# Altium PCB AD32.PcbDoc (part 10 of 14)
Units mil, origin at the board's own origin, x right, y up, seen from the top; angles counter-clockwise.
Board outline 7007.87 x 4368.85 mil, 12 copper layers (Top Layer, Int1 (GND), Int2 (AVDD), Int3 (DVDD), Int4 (GND), Int5 (ST), Int6 (SB), Int8 (AGND), Int7 (AVCC), Int9 (VCCA), Int10 (GND), Bottom Layer), stack 60.136 mil thick; 1350 components, 880 nets, 4712 pads, 2835 vias.
Unrouted connection lines stored in the file: 19.
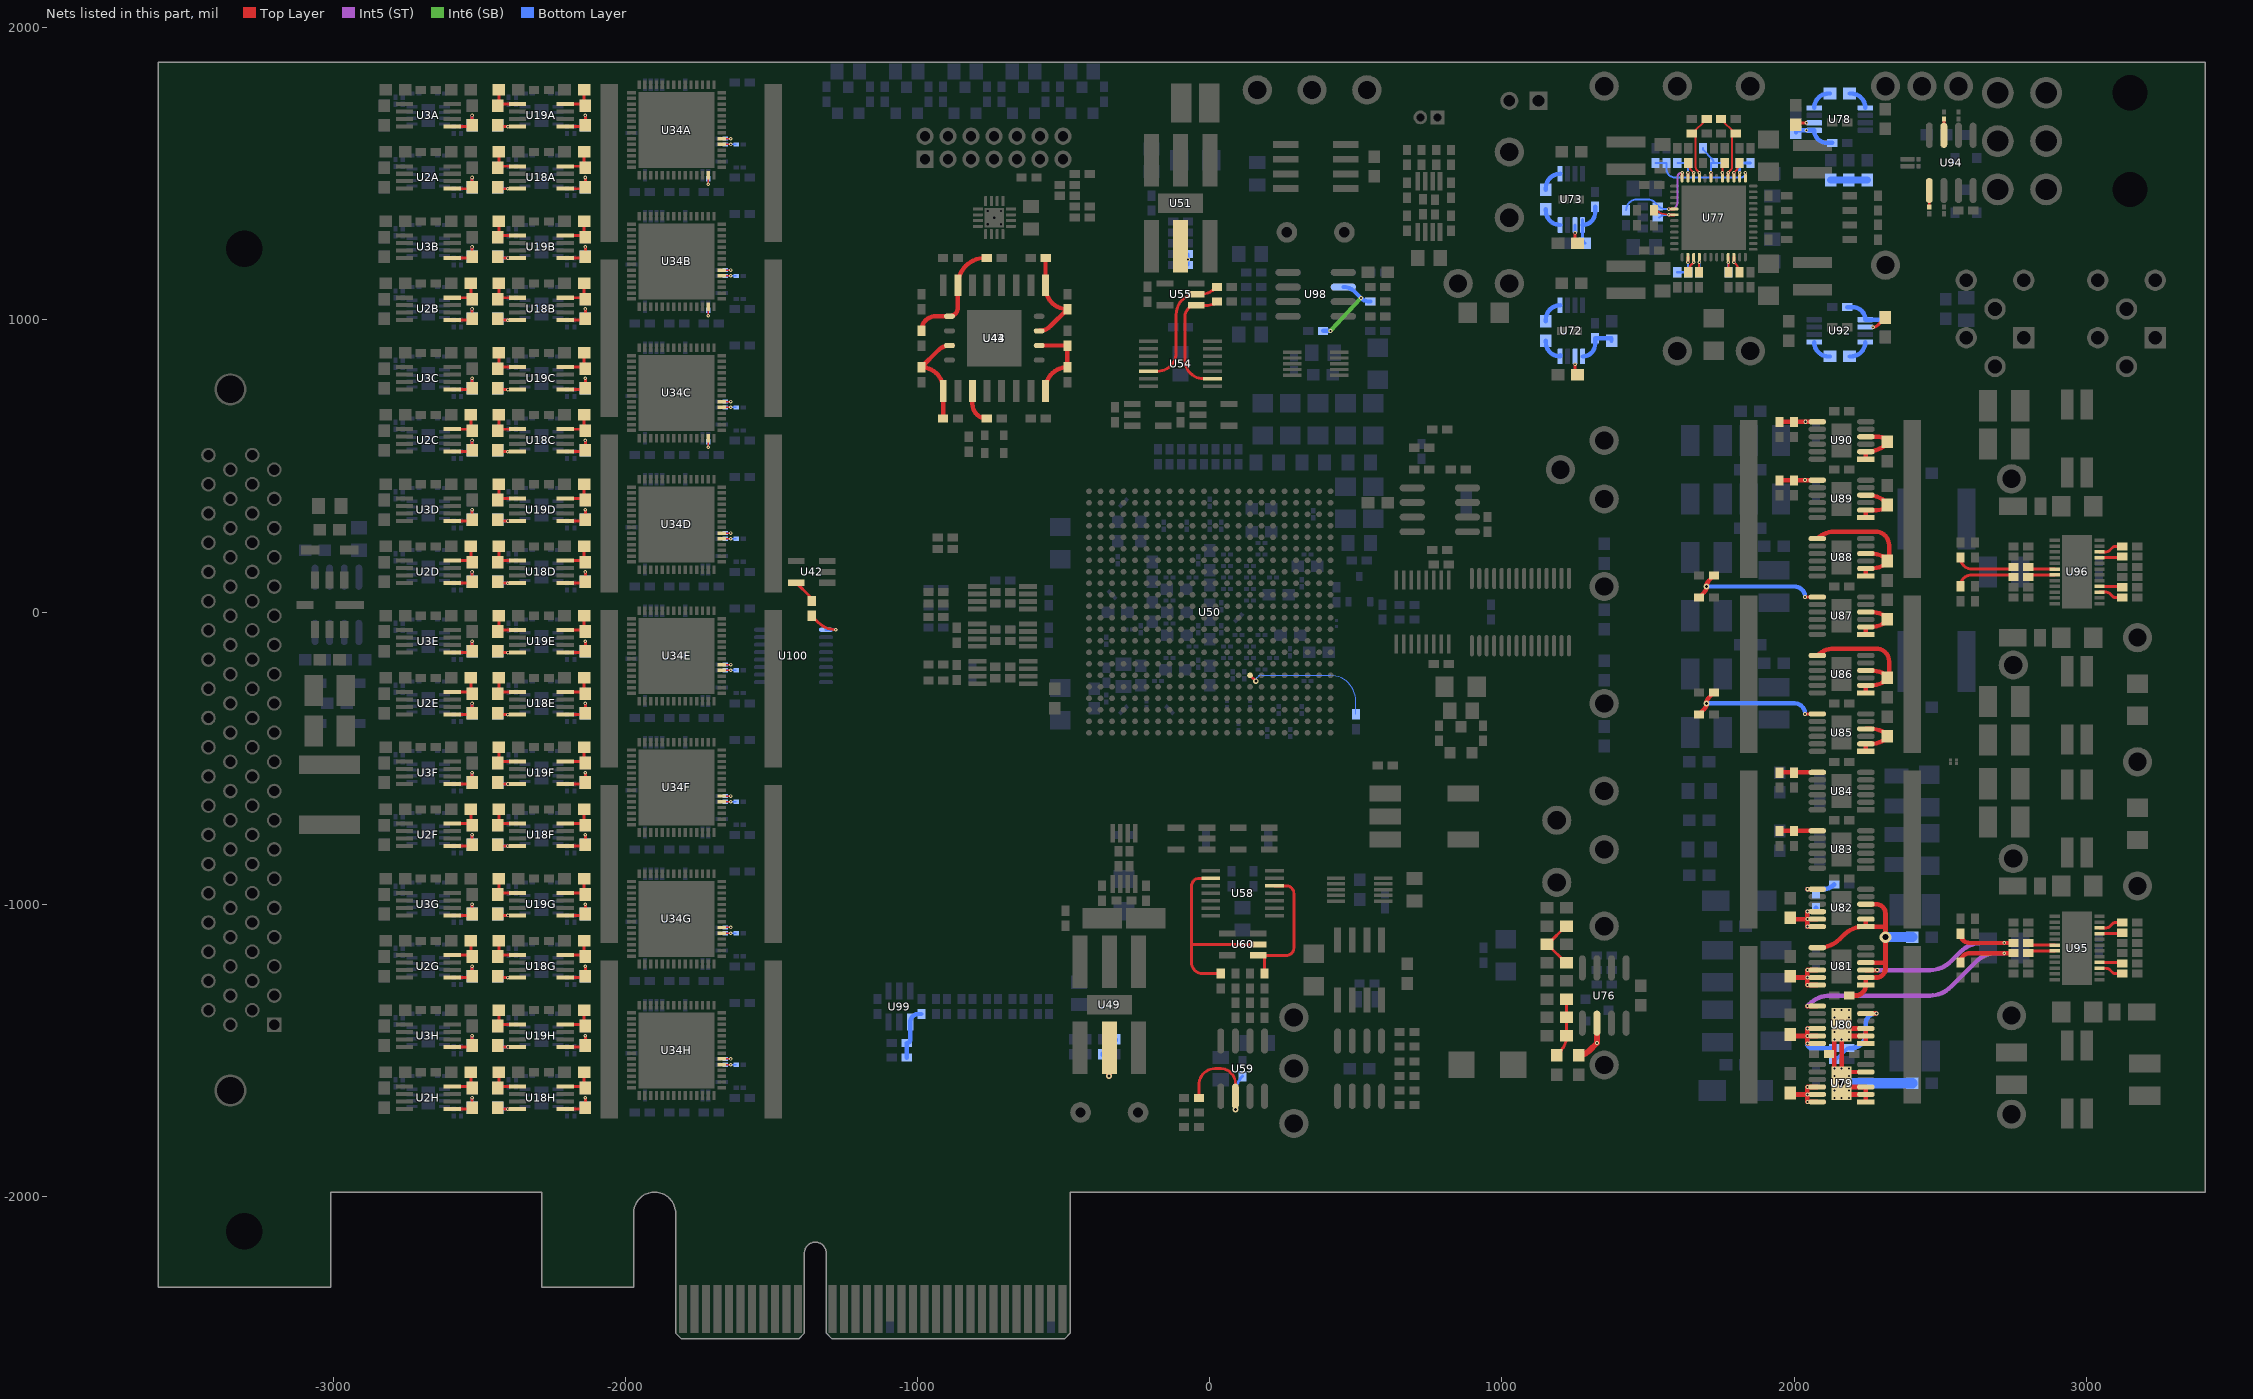
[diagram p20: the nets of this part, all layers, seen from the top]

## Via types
v1: diameter 12, hole 6, Top Layer to Bottom Layer, tented both sides, 1497 vias
v2: diameter 20, hole 10, Top Layer to Bottom Layer, tented both sides, 364 vias
v3: diameter 19, hole 10, Top Layer to Bottom Layer, tented both sides, 347 vias
v4: diameter 14, hole 7, Top Layer to Bottom Layer, tented both sides, 228 vias
v5: diameter 19.68, hole 7.87, Top Layer to Bottom Layer, 225 vias
v6: diameter 19.02, hole 10, Top Layer to Bottom Layer, tented both sides, 85 vias
v7: diameter 20, hole 10, Top Layer to Bottom Layer, 32 vias
v8: diameter 40, hole 20, Top Layer to Bottom Layer, tented both sides, 14 vias
v9: diameter 30, hole 15, Top Layer to Bottom Layer, tented both sides, 12 vias
v10: diameter 25, hole 13, Top Layer to Bottom Layer, 8 vias
v11: diameter 40, hole 20, Top Layer to Bottom Layer, 6 vias
v12: diameter 50, hole 20, Top Layer to Bottom Layer, 6 vias
v13: diameter 66, hole 47, Top Layer to Bottom Layer, tented both sides, 3 vias
v14: diameter 63, hole 45, Top Layer to Bottom Layer, 2 vias
v15: diameter 50, hole 25, Top Layer to Bottom Layer, 2 vias
v16: diameter 12, hole 6, Top Layer to Bottom Layer, 2 vias
v17: diameter 60, hole 40, Top Layer to Bottom Layer, tented both sides, 1 vias
v18: diameter 60, hole 40, Top Layer to Bottom Layer, 1 vias

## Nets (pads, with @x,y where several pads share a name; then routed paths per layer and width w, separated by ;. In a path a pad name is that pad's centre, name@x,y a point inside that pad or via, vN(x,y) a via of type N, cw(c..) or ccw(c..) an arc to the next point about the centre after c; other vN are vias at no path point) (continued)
NetR44B_1: R44B.1 R60B.2 U2B.4 | length 118.6
  Top Layer w10: U2B.4@-2593.31,1075.89 -2530.92,1075.89 R60B.2@-2529.92,1076.89 ; R60B.2@-2529.04,1076 -2525,1071.97 R60B.2@-2525,1070.96 ; R60B.2@-2529.04,1076.89 R44B.1@-2529.04,1125
NetR44C_1: R44C.1 R60C.2 U2C.4 | length 118.6
  Top Layer w10: U2C.4@-2593.31,625.89 -2530.92,625.89 R60C.2@-2529.92,626.89 ; R60C.2@-2529.04,626 -2525,621.97 R60C.2@-2525,620.96 ; R60C.2@-2529.04,626.89 R44C.1@-2529.04,675
NetR44D_1: R44D.1 R60D.2 U2D.4 | length 118.6
  Top Layer w10: U2D.4@-2593.31,175.89 -2530.92,175.89 R60D.2@-2529.92,176.89 ; R60D.2@-2529.04,176 -2525,171.97 R60D.2@-2525,170.96 ; R60D.2@-2529.04,176.89 R44D.1@-2529.04,225
NetR44E_1: R44E.1 R60E.2 U2E.4 | length 118.6
  Top Layer w10: U2E.4@-2593.31,-274.11 -2530.92,-274.11 R60E.2@-2529.92,-273.11 ; R60E.2@-2529.04,-274 -2525,-278.03 R60E.2@-2525,-279.04 ; R60E.2@-2529.04,-273.11 R44E.1@-2529.04,-225
NetR44F_1: R44F.1 R60F.2 U2F.4 | length 118.6
  Top Layer w10: U2F.4@-2593.31,-724.11 -2530.92,-724.11 R60F.2@-2529.92,-723.11 ; R60F.2@-2529.04,-724 -2525,-728.03 R60F.2@-2525,-729.04 ; R60F.2@-2529.04,-723.11 R44F.1@-2529.04,-675
NetR44G_1: R44G.1 R60G.2 U2G.4 | length 118.6
  Top Layer w10: U2G.4@-2593.31,-1174.11 -2530.92,-1174.11 R60G.2@-2529.92,-1173.11 ; R60G.2@-2529.04,-1174 -2525,-1178.03 R60G.2@-2525,-1179.04 ; R60G.2@-2529.04,-1173.11 R44G.1@-2529.04,-1125
NetR44H_1: R44H.1 R60H.2 U2H.4 | length 118.6
  Top Layer w10: U2H.4@-2593.31,-1624.11 -2530.92,-1624.11 R60H.2@-2529.92,-1623.11 ; R60H.2@-2529.04,-1624 -2525,-1628.03 R60H.2@-2525,-1629.04 ; R60H.2@-2529.04,-1623.11 R44H.1@-2529.04,-1575
NetR52A_1: R52A.1 R609A.2 U3A.1 | length 136.6
  Top Layer w10: U3A.1@-2593.31,1661.49 -2537.18,1661.49 ccw(c-2537.18,1678.72) R52A.1@-2525,1666.54 v1(-2525,1700)
  Bottom Layer w10: R609A.2@-2525,1666.54 v1(-2525,1700)
NetR52B_1: R52B.1 R609B.2 U3B.1 | length 136.6
  Top Layer w10: U3B.1@-2593.31,1211.49 -2537.18,1211.49 ccw(c-2537.18,1228.72) R52B.1@-2525,1216.54 v1(-2525,1250)
  Bottom Layer w10: R609B.2@-2525,1216.54 v1(-2525,1250)
NetR52C_1: R52C.1 R609C.2 U3C.1 | length 136.6
  Top Layer w10: U3C.1@-2593.31,761.49 -2537.18,761.49 ccw(c-2537.18,778.72) R52C.1@-2525,766.54 v1(-2525,800)
  Bottom Layer w10: R609C.2@-2525,766.54 v1(-2525,800)
NetR52D_1: R52D.1 R609D.2 U3D.1 | length 136.6
  Top Layer w10: U3D.1@-2593.31,311.49 -2537.18,311.49 ccw(c-2537.18,328.72) R52D.1@-2525,316.54 v1(-2525,350)
  Bottom Layer w10: R609D.2@-2525,316.54 v1(-2525,350)
NetR52E_1: R52E.1 R609E.2 U3E.1 | length 136.6
  Top Layer w10: U3E.1@-2593.31,-138.51 -2537.18,-138.51 ccw(c-2537.18,-121.28) R52E.1@-2525,-133.46 v1(-2525,-100)
  Bottom Layer w10: R609E.2@-2525,-133.46 v1(-2525,-100)
NetR52F_1: R52F.1 R609F.2 U3F.1 | length 136.6
  Top Layer w10: U3F.1@-2593.31,-588.51 -2537.18,-588.51 ccw(c-2537.18,-571.28) R52F.1@-2525,-583.46 v1(-2525,-550)
  Bottom Layer w10: R609F.2@-2525,-583.46 v1(-2525,-550)
NetR52G_1: R52G.1 R609G.2 U3G.1 | length 136.6
  Top Layer w10: U3G.1@-2593.31,-1038.51 -2537.18,-1038.51 ccw(c-2537.18,-1021.28) R52G.1@-2525,-1033.46 v1(-2525,-1000)
  Bottom Layer w10: R609G.2@-2525,-1033.46 v1(-2525,-1000)
NetR52H_1: R52H.1 R609H.2 U3H.1 | length 136.6
  Top Layer w10: U3H.1@-2593.31,-1488.51 -2537.18,-1488.51 ccw(c-2537.18,-1471.28) R52H.1@-2525,-1483.46 v1(-2525,-1450)
  Bottom Layer w10: R609H.2@-2525,-1483.46 v1(-2525,-1450)
NetR60A_1: R60A.1 R601A.2 U2A.1 | length 136.6
  Top Layer w10: U2A.1@-2593.31,1449.11 -2536.88,1449.11 ccw(c-2536.88,1465.92) R60A.1@-2525,1454.04 v1(-2525,1487.5)
  Bottom Layer w10: R601A.2@-2525,1454.04 v1(-2525,1487.5)
NetR60B_1: R60B.1 R601B.2 U2B.1 | length 136.6
  Top Layer w10: U2B.1@-2593.31,999.11 -2536.88,999.11 ccw(c-2536.88,1015.92) R60B.1@-2525,1004.04 v1(-2525,1037.5)
  Bottom Layer w10: R601B.2@-2525,1004.04 v1(-2525,1037.5)
NetR60C_1: R60C.1 R601C.2 U2C.1 | length 136.6
  Top Layer w10: U2C.1@-2593.31,549.11 -2536.88,549.11 ccw(c-2536.88,565.92) R60C.1@-2525,554.04 v1(-2525,587.5)
  Bottom Layer w10: R601C.2@-2525,554.04 v1(-2525,587.5)
NetR60D_1: R60D.1 R601D.2 U2D.1 | length 136.6
  Top Layer w10: U2D.1@-2593.31,99.11 -2536.88,99.11 ccw(c-2536.88,115.92) R60D.1@-2525,104.04 v1(-2525,137.5)
  Bottom Layer w10: R601D.2@-2525,104.04 v1(-2525,137.5)
NetR60E_1: R60E.1 R601E.2 U2E.1 | length 136.6
  Top Layer w10: U2E.1@-2593.31,-350.89 -2536.88,-350.89 ccw(c-2536.88,-334.08) R60E.1@-2525,-345.96 v1(-2525,-312.5)
  Bottom Layer w10: R601E.2@-2525,-345.96 v1(-2525,-312.5)
NetR60F_1: R60F.1 R601F.2 U2F.1 | length 136.6
  Top Layer w10: U2F.1@-2593.31,-800.89 -2536.88,-800.89 ccw(c-2536.88,-784.08) R60F.1@-2525,-795.96 v1(-2525,-762.5)
  Bottom Layer w10: R601F.2@-2525,-795.96 v1(-2525,-762.5)
NetR60G_1: R60G.1 R601G.2 U2G.1 | length 136.6
  Top Layer w10: U2G.1@-2593.31,-1250.89 -2536.88,-1250.89 ccw(c-2536.88,-1234.08) R60G.1@-2525,-1245.96 v1(-2525,-1212.5)
  Bottom Layer w10: R601G.2@-2525,-1245.96 v1(-2525,-1212.5)
NetR60H_1: R60H.1 R601H.2 U2H.1 | length 136.6
  Top Layer w10: U2H.1@-2593.31,-1700.89 -2536.88,-1700.89 ccw(c-2536.88,-1684.08) R60H.1@-2525,-1695.96 v1(-2525,-1662.5)
  Bottom Layer w10: R601H.2@-2525,-1695.96 v1(-2525,-1662.5)
NetR68A_1: R68A.1 R593A.2 U19A.8 | length 107.4
  Top Layer w10: R68A.1@-2437.5,1667.04 ccw(c-2432.58,1667.04) -2432.58,1662.11 -2402.5,1662.11 U19A.8@-2369.19,1662.11
  Bottom Layer w10: R593A.2@-2437.5,1666.54 ccw(c-2425.62,1678.42) -2425.62,1661.61 v1(-2402.5,1661.61)
NetR68A_2: R68A.2 R84A.1 U19A.5 | length 127.5
  Top Layer w10: R68A.2@-2433.46,1738.39 R68A.2@-2433.46,1738.31 ; R68A.2@-2433.46,1738.81 cw(c-2432.58,1733.96) -2432.58,1738.89 U19A.5@-2369.19,1738.89 ; R68A.2@-2433.46,1738.89 R84A.1@-2433.46,1788 ; R68A.2@-2433.46,1738.31 ccw(c-2432.58,1733.46) R68A.2@-2437.5,1733.46 ccw(c-2437.5,1737.5) -2433.46,1737.5 R68A.2@-2433.46,1738.31
NetR68B_1: R68B.1 R593B.2 U19B.8 | length 107.4
  Top Layer w10: R68B.1@-2437.5,1217.04 ccw(c-2432.58,1217.04) -2432.58,1212.11 -2402.5,1212.11 U19B.8@-2369.19,1212.11
  Bottom Layer w10: R593B.2@-2437.5,1216.54 ccw(c-2425.62,1228.42) -2425.62,1211.61 v1(-2402.5,1211.61)
NetR68B_2: R68B.2 R84B.1 U19B.5 | length 127.5
  Top Layer w10: R68B.2@-2433.46,1288.39 R68B.2@-2433.46,1288.31 ; R68B.2@-2433.46,1288.81 cw(c-2432.58,1283.96) -2432.58,1288.89 U19B.5@-2369.19,1288.89 ; R68B.2@-2433.46,1288.89 R84B.1@-2433.46,1338 ; R68B.2@-2433.46,1288.31 ccw(c-2432.58,1283.46) R68B.2@-2437.5,1283.46 ccw(c-2437.5,1287.5) -2433.46,1287.5 R68B.2@-2433.46,1288.31
NetR68C_1: R68C.1 R593C.2 U19C.8 | length 107.4
  Top Layer w10: R68C.1@-2437.5,767.04 ccw(c-2432.58,767.04) -2432.58,762.11 -2402.5,762.11 U19C.8@-2369.19,762.11
  Bottom Layer w10: R593C.2@-2437.5,766.54 ccw(c-2425.62,778.42) -2425.62,761.61 v1(-2402.5,761.61)
NetR68C_2: R68C.2 R84C.1 U19C.5 | length 127.5
  Top Layer w10: R68C.2@-2433.46,838.39 R68C.2@-2433.46,838.31 ; R68C.2@-2433.46,838.81 cw(c-2432.58,833.96) -2432.58,838.89 U19C.5@-2369.19,838.89 ; R68C.2@-2433.46,838.89 R84C.1@-2433.46,888 ; R68C.2@-2433.46,838.31 ccw(c-2432.58,833.46) R68C.2@-2437.5,833.46 ccw(c-2437.5,837.5) -2433.46,837.5 R68C.2@-2433.46,838.31
NetR68D_1: R68D.1 R593D.2 U19D.8 | length 107.4
  Top Layer w10: R68D.1@-2437.5,317.04 ccw(c-2432.58,317.04) -2432.58,312.11 -2402.5,312.11 U19D.8@-2369.19,312.11
  Bottom Layer w10: R593D.2@-2437.5,316.54 ccw(c-2425.62,328.42) -2425.62,311.61 v1(-2402.5,311.61)
NetR68D_2: R68D.2 R84D.1 U19D.5 | length 127.5
  Top Layer w10: R68D.2@-2433.46,388.39 R68D.2@-2433.46,388.31 ; R68D.2@-2433.46,388.81 cw(c-2432.58,383.96) -2432.58,388.89 U19D.5@-2369.19,388.89 ; R68D.2@-2433.46,388.89 R84D.1@-2433.46,438 ; R68D.2@-2433.46,388.31 ccw(c-2432.58,383.46) R68D.2@-2437.5,383.46 ccw(c-2437.5,387.5) -2433.46,387.5 R68D.2@-2433.46,388.31
NetR68E_1: R68E.1 R593E.2 U19E.8 | length 107.4
  Top Layer w10: R68E.1@-2437.5,-132.96 ccw(c-2432.58,-132.96) -2432.58,-137.89 -2402.5,-137.89 U19E.8@-2369.19,-137.89
  Bottom Layer w10: R593E.2@-2437.5,-133.46 ccw(c-2425.62,-121.58) -2425.62,-138.39 v1(-2402.5,-138.39)
NetR68E_2: R68E.2 R84E.1 U19E.5 | length 127.5
  Top Layer w10: R68E.2@-2433.46,-61.61 R68E.2@-2433.46,-61.69 ; R68E.2@-2433.46,-61.19 cw(c-2432.58,-66.04) -2432.58,-61.11 U19E.5@-2369.19,-61.11 ; R68E.2@-2433.46,-61.11 R84E.1@-2433.46,-12 ; R68E.2@-2433.46,-61.69 ccw(c-2432.58,-66.54) R68E.2@-2437.5,-66.54 ccw(c-2437.5,-62.5) -2433.46,-62.5 R68E.2@-2433.46,-61.69
NetR68F_1: R68F.1 R593F.2 U19F.8 | length 107.4
  Top Layer w10: R68F.1@-2437.5,-582.96 ccw(c-2432.58,-582.96) -2432.58,-587.89 -2402.5,-587.89 U19F.8@-2369.19,-587.89
  Bottom Layer w10: R593F.2@-2437.5,-583.46 ccw(c-2425.62,-571.58) -2425.62,-588.39 v1(-2402.5,-588.39)
NetR68F_2: R68F.2 R84F.1 U19F.5 | length 127.5
  Top Layer w10: R68F.2@-2433.46,-511.61 R68F.2@-2433.46,-511.69 ; R68F.2@-2433.46,-511.19 cw(c-2432.58,-516.04) -2432.58,-511.11 U19F.5@-2369.19,-511.11 ; R68F.2@-2433.46,-511.11 R84F.1@-2433.46,-462 ; R68F.2@-2433.46,-511.69 ccw(c-2432.58,-516.54) R68F.2@-2437.5,-516.54 ccw(c-2437.5,-512.5) -2433.46,-512.5 R68F.2@-2433.46,-511.69
NetR68G_1: R68G.1 R593G.2 U19G.8 | length 107.4
  Top Layer w10: R68G.1@-2437.5,-1032.96 ccw(c-2432.58,-1032.96) -2432.58,-1037.89 -2402.5,-1037.89 U19G.8@-2369.19,-1037.89
  Bottom Layer w10: R593G.2@-2437.5,-1033.46 ccw(c-2425.62,-1021.58) -2425.62,-1038.39 v1(-2402.5,-1038.39)
NetR68G_2: R68G.2 R84G.1 U19G.5 | length 127.5
  Top Layer w10: R68G.2@-2433.46,-961.61 R68G.2@-2433.46,-961.69 ; R68G.2@-2433.46,-961.19 cw(c-2432.58,-966.04) -2432.58,-961.11 U19G.5@-2369.19,-961.11 ; R68G.2@-2433.46,-961.11 R84G.1@-2433.46,-912 ; R68G.2@-2433.46,-961.69 ccw(c-2432.58,-966.54) R68G.2@-2437.5,-966.54 ccw(c-2437.5,-962.5) -2433.46,-962.5 R68G.2@-2433.46,-961.69
NetR68H_1: R68H.1 R593H.2 U19H.8 | length 107.4
  Top Layer w10: R68H.1@-2437.5,-1482.96 ccw(c-2432.58,-1482.96) -2432.58,-1487.89 -2402.5,-1487.89 U19H.8@-2369.19,-1487.89
  Bottom Layer w10: R593H.2@-2437.5,-1483.46 ccw(c-2425.62,-1471.58) -2425.62,-1488.39 v1(-2402.5,-1488.39)
NetR68H_2: R68H.2 R84H.1 U19H.5 | length 127.5
  Top Layer w10: R68H.2@-2433.46,-1411.61 R68H.2@-2433.46,-1411.69 ; R68H.2@-2433.46,-1411.19 cw(c-2432.58,-1416.04) -2432.58,-1411.11 U19H.5@-2369.19,-1411.11 ; R68H.2@-2433.46,-1411.11 R84H.1@-2433.46,-1362 ; R68H.2@-2433.46,-1411.69 ccw(c-2432.58,-1416.54) R68H.2@-2437.5,-1416.54 ccw(c-2437.5,-1412.5) -2433.46,-1412.5 R68H.2@-2433.46,-1411.69
NetR76A_1: R76A.1 R585A.2 U18A.8 | length 108.5
  Top Layer w10: R76A.1@-2437.5,1454.04 ccw(c-2432.58,1454.04) -2432.58,1449.11 v1(-2402.89,1449.11) U18A.8@-2369.19,1449.11
  Bottom Layer w10: R585A.2@-2437.5,1454.04 ccw(c-2432.58,1454.04) -2432.58,1449.11 v1(-2402.89,1449.11)
NetR76A_2: R76A.2 R92A.1 U18A.5 | length 124.7
  Top Layer w10: R92A.1@-2433.46,1575 -2433.46,1530.71 cw(c-2447.24,1530.71) R76A.2@-2437.5,1520.96 cw(c-2425.62,1509.08) -2425.62,1525.89 U18A.5@-2369.19,1525.89
NetR76B_1: R76B.1 R585B.2 U18B.8 | length 108.5
  Top Layer w10: R76B.1@-2437.5,1004.04 ccw(c-2432.58,1004.04) -2432.58,999.11 v1(-2402.89,999.11) U18B.8@-2369.19,999.11
  Bottom Layer w10: R585B.2@-2437.5,1004.04 ccw(c-2432.58,1004.04) -2432.58,999.11 v1(-2402.89,999.11)
NetR76B_2: R76B.2 R92B.1 U18B.5 | length 124.7
  Top Layer w10: R92B.1@-2433.46,1125 -2433.46,1080.71 cw(c-2447.24,1080.71) R76B.2@-2437.5,1070.96 cw(c-2425.62,1059.08) -2425.62,1075.89 U18B.5@-2369.19,1075.89
NetR76C_1: R76C.1 R585C.2 U18C.8 | length 108.5
  Top Layer w10: R76C.1@-2437.5,554.04 ccw(c-2432.58,554.04) -2432.58,549.11 v1(-2402.89,549.11) U18C.8@-2369.19,549.11
  Bottom Layer w10: R585C.2@-2437.5,554.04 ccw(c-2432.58,554.04) -2432.58,549.11 v1(-2402.89,549.11)
NetR76C_2: R76C.2 R92C.1 U18C.5 | length 124.7
  Top Layer w10: R92C.1@-2433.46,675 -2433.46,630.71 cw(c-2447.24,630.71) R76C.2@-2437.5,620.96 cw(c-2425.62,609.08) -2425.62,625.89 U18C.5@-2369.19,625.89
NetR76D_1: R76D.1 R585D.2 U18D.8 | length 108.5
  Top Layer w10: R76D.1@-2437.5,104.04 ccw(c-2432.58,104.04) -2432.58,99.11 v1(-2402.89,99.11) U18D.8@-2369.19,99.11
  Bottom Layer w10: R585D.2@-2437.5,104.04 ccw(c-2432.58,104.04) -2432.58,99.11 v1(-2402.89,99.11)
NetR76D_2: R76D.2 R92D.1 U18D.5 | length 124.7
  Top Layer w10: R92D.1@-2433.46,225 -2433.46,180.71 cw(c-2447.24,180.71) R76D.2@-2437.5,170.96 cw(c-2425.62,159.08) -2425.62,175.89 U18D.5@-2369.19,175.89
NetR76E_1: R76E.1 R585E.2 U18E.8 | length 108.5
  Top Layer w10: R76E.1@-2437.5,-345.96 ccw(c-2432.58,-345.96) -2432.58,-350.89 v1(-2402.89,-350.89) U18E.8@-2369.19,-350.89
  Bottom Layer w10: R585E.2@-2437.5,-345.96 ccw(c-2432.58,-345.96) -2432.58,-350.89 v1(-2402.89,-350.89)
NetR76E_2: R76E.2 R92E.1 U18E.5 | length 124.7
  Top Layer w10: R92E.1@-2433.46,-225 -2433.46,-269.29 cw(c-2447.24,-269.29) R76E.2@-2437.5,-279.04 cw(c-2425.62,-290.92) -2425.62,-274.11 U18E.5@-2369.19,-274.11
NetR76F_1: R76F.1 R585F.2 U18F.8 | length 108.5
  Top Layer w10: R76F.1@-2437.5,-795.96 ccw(c-2432.58,-795.96) -2432.58,-800.89 v1(-2402.89,-800.89) U18F.8@-2369.19,-800.89
  Bottom Layer w10: R585F.2@-2437.5,-795.96 ccw(c-2432.58,-795.96) -2432.58,-800.89 v1(-2402.89,-800.89)
NetR76F_2: R76F.2 R92F.1 U18F.5 | length 124.7
  Top Layer w10: R92F.1@-2433.46,-675 -2433.46,-719.29 cw(c-2447.24,-719.29) R76F.2@-2437.5,-729.04 cw(c-2425.62,-740.92) -2425.62,-724.11 U18F.5@-2369.19,-724.11
NetR76G_1: R76G.1 R585G.2 U18G.8 | length 108.5
  Top Layer w10: R76G.1@-2437.5,-1245.96 ccw(c-2432.58,-1245.96) -2432.58,-1250.89 v1(-2402.89,-1250.89) U18G.8@-2369.19,-1250.89
  Bottom Layer w10: R585G.2@-2437.5,-1245.96 ccw(c-2432.58,-1245.96) -2432.58,-1250.89 v1(-2402.89,-1250.89)
NetR76G_2: R76G.2 R92G.1 U18G.5 | length 124.7
  Top Layer w10: R92G.1@-2433.46,-1125 -2433.46,-1169.29 cw(c-2447.24,-1169.29) R76G.2@-2437.5,-1179.04 cw(c-2425.62,-1190.92) -2425.62,-1174.11 U18G.5@-2369.19,-1174.11
NetR76H_1: R76H.1 R585H.2 U18H.8 | length 108.5
  Top Layer w10: R76H.1@-2437.5,-1695.96 ccw(c-2432.58,-1695.96) -2432.58,-1700.89 v1(-2402.89,-1700.89) U18H.8@-2369.19,-1700.89
  Bottom Layer w10: R585H.2@-2437.5,-1695.96 ccw(c-2432.58,-1695.96) -2432.58,-1700.89 v1(-2402.89,-1700.89)
NetR76H_2: R76H.2 R92H.1 U18H.5 | length 124.7
  Top Layer w10: R92H.1@-2433.46,-1575 -2433.46,-1619.29 cw(c-2447.24,-1619.29) R76H.2@-2437.5,-1629.04 cw(c-2425.62,-1640.92) -2425.62,-1624.11 U18H.5@-2369.19,-1624.11
NetR100A_1: R100A.1 R116A.2 U19A.4 | length 127.5
  Top Layer w10: U19A.4@-2205.81,1738.89 -2142.42,1738.89 cw(c-2142.42,1733.96) -2141.54,1738.81 -2141.54,1738.89 R100A.1@-2141.54,1788 ; R116A.2@-2141.54,1737.5 ccw(c-2137.5,1737.5) R116A.2@-2137.5,1733.46 ccw(c-2142.42,1733.46) -2141.54,1738.31 R116A.2@-2141.54,1737.5
NetR100B_1: R100B.1 R116B.2 U19B.4 | length 127.5
  Top Layer w10: U19B.4@-2205.81,1288.89 -2142.42,1288.89 cw(c-2142.42,1283.96) -2141.54,1288.81 -2141.54,1288.89 R100B.1@-2141.54,1338 ; R116B.2@-2141.54,1287.5 ccw(c-2137.5,1287.5) R116B.2@-2137.5,1283.46 ccw(c-2142.42,1283.46) -2141.54,1288.31 R116B.2@-2141.54,1287.5
NetR100C_1: R100C.1 R116C.2 U19C.4 | length 127.5
  Top Layer w10: U19C.4@-2205.81,838.89 -2142.42,838.89 cw(c-2142.42,833.96) -2141.54,838.81 -2141.54,838.89 R100C.1@-2141.54,888 ; R116C.2@-2141.54,837.5 ccw(c-2137.5,837.5) R116C.2@-2137.5,833.46 ccw(c-2142.42,833.46) -2141.54,838.31 R116C.2@-2141.54,837.5
NetR100D_1: R100D.1 R116D.2 U19D.4 | length 127.5
  Top Layer w10: U19D.4@-2205.81,388.89 -2142.42,388.89 cw(c-2142.42,383.96) -2141.54,388.81 -2141.54,388.89 R100D.1@-2141.54,438 ; R116D.2@-2141.54,387.5 ccw(c-2137.5,387.5) R116D.2@-2137.5,383.46 ccw(c-2142.42,383.46) -2141.54,388.31 R116D.2@-2141.54,387.5
NetR100E_1: R100E.1 R116E.2 U19E.4 | length 127.5
  Top Layer w10: U19E.4@-2205.81,-61.11 -2142.42,-61.11 cw(c-2142.42,-66.04) -2141.54,-61.19 -2141.54,-61.11 R100E.1@-2141.54,-12 ; R116E.2@-2141.54,-62.5 ccw(c-2137.5,-62.5) R116E.2@-2137.5,-66.54 ccw(c-2142.42,-66.54) -2141.54,-61.69 R116E.2@-2141.54,-62.5
NetR100F_1: R100F.1 R116F.2 U19F.4 | length 127.5
  Top Layer w10: U19F.4@-2205.81,-511.11 -2142.42,-511.11 cw(c-2142.42,-516.04) -2141.54,-511.19 -2141.54,-511.11 R100F.1@-2141.54,-462 ; R116F.2@-2141.54,-512.5 ccw(c-2137.5,-512.5) R116F.2@-2137.5,-516.54 ccw(c-2142.42,-516.54) -2141.54,-511.69 R116F.2@-2141.54,-512.5
NetR100G_1: R100G.1 R116G.2 U19G.4 | length 127.5
  Top Layer w10: U19G.4@-2205.81,-961.11 -2142.42,-961.11 cw(c-2142.42,-966.04) -2141.54,-961.19 -2141.54,-961.11 R100G.1@-2141.54,-912 ; R116G.2@-2141.54,-962.5 ccw(c-2137.5,-962.5) R116G.2@-2137.5,-966.54 ccw(c-2142.42,-966.54) -2141.54,-961.69 R116G.2@-2141.54,-962.5
NetR100H_1: R100H.1 R116H.2 U19H.4 | length 127.5
  Top Layer w10: U19H.4@-2205.81,-1411.11 -2142.42,-1411.11 cw(c-2142.42,-1416.04) -2141.54,-1411.19 -2141.54,-1411.11 R100H.1@-2141.54,-1362 ; R116H.2@-2141.54,-1412.5 ccw(c-2137.5,-1412.5) R116H.2@-2137.5,-1416.54 ccw(c-2142.42,-1416.54) -2141.54,-1411.69 R116H.2@-2141.54,-1412.5
NetR108A_1: R108A.1 R124A.2 U18A.4 | length 124.7
  Top Layer w10: U18A.4@-2205.81,1525.89 -2149.38,1525.89 cw(c-2149.38,1509.08) R124A.2@-2137.5,1520.96 cw(c-2127.76,1530.71) -2141.54,1530.71 R108A.1@-2141.54,1575
NetR108B_1: R108B.1 R124B.2 U18B.4 | length 124.7
  Top Layer w10: U18B.4@-2205.81,1075.89 -2149.38,1075.89 cw(c-2149.38,1059.08) R124B.2@-2137.5,1070.96 cw(c-2127.76,1080.71) -2141.54,1080.71 R108B.1@-2141.54,1125
NetR108C_1: R108C.1 R124C.2 U18C.4 | length 124.7
  Top Layer w10: U18C.4@-2205.81,625.89 -2149.38,625.89 cw(c-2149.38,609.08) R124C.2@-2137.5,620.96 cw(c-2127.76,630.71) -2141.54,630.71 R108C.1@-2141.54,675
NetR108D_1: R108D.1 R124D.2 U18D.4 | length 124.7
  Top Layer w10: U18D.4@-2205.81,175.89 -2149.38,175.89 cw(c-2149.38,159.08) R124D.2@-2137.5,170.96 cw(c-2127.76,180.71) -2141.54,180.71 R108D.1@-2141.54,225
NetR108E_1: R108E.1 R124E.2 U18E.4 | length 124.7
  Top Layer w10: U18E.4@-2205.81,-274.11 -2149.38,-274.11 cw(c-2149.38,-290.92) R124E.2@-2137.5,-279.04 cw(c-2127.76,-269.29) -2141.54,-269.29 R108E.1@-2141.54,-225
NetR108F_1: R108F.1 R124F.2 U18F.4 | length 124.7
  Top Layer w10: U18F.4@-2205.81,-724.11 -2149.38,-724.11 cw(c-2149.38,-740.92) R124F.2@-2137.5,-729.04 cw(c-2127.76,-719.29) -2141.54,-719.29 R108F.1@-2141.54,-675
NetR108G_1: R108G.1 R124G.2 U18G.4 | length 124.7
  Top Layer w10: U18G.4@-2205.81,-1174.11 -2149.38,-1174.11 cw(c-2149.38,-1190.92) R124G.2@-2137.5,-1179.04 cw(c-2127.76,-1169.29) -2141.54,-1169.29 R108G.1@-2141.54,-1125
NetR108H_1: R108H.1 R124H.2 U18H.4 | length 124.7
  Top Layer w10: U18H.4@-2205.81,-1624.11 -2149.38,-1624.11 cw(c-2149.38,-1640.92) R124H.2@-2137.5,-1629.04 cw(c-2127.76,-1619.29) -2141.54,-1619.29 R108H.1@-2141.54,-1575
NetR116A_1: R116A.1 R538A.2 U19A.1 | length 136.6
  Top Layer w10: U19A.1@-2205.81,1661.61 -2149.38,1661.61 ccw(c-2149.38,1678.42) R116A.1@-2137.5,1666.54 v1(-2137.5,1700)
  Bottom Layer w10: R538A.2@-2137.5,1666.54 v1(-2137.5,1700)
NetR116B_1: R116B.1 R538B.2 U19B.1 | length 136.6
  Top Layer w10: U19B.1@-2205.81,1211.61 -2149.38,1211.61 ccw(c-2149.38,1228.42) R116B.1@-2137.5,1216.54 v1(-2137.5,1250)
  Bottom Layer w10: R538B.2@-2137.5,1216.54 v1(-2137.5,1250)
NetR116C_1: R116C.1 R538C.2 U19C.1 | length 136.6
  Top Layer w10: U19C.1@-2205.81,761.61 -2149.38,761.61 ccw(c-2149.38,778.42) R116C.1@-2137.5,766.54 v1(-2137.5,800)
  Bottom Layer w10: R538C.2@-2137.5,766.54 v1(-2137.5,800)
NetR116D_1: R116D.1 R538D.2 U19D.1 | length 136.6
  Top Layer w10: U19D.1@-2205.81,311.61 -2149.38,311.61 ccw(c-2149.38,328.42) R116D.1@-2137.5,316.54 v1(-2137.5,350)
  Bottom Layer w10: R538D.2@-2137.5,316.54 v1(-2137.5,350)
NetR116E_1: R116E.1 R538E.2 U19E.1 | length 136.6
  Top Layer w10: U19E.1@-2205.81,-138.39 -2149.38,-138.39 ccw(c-2149.38,-121.58) R116E.1@-2137.5,-133.46 v1(-2137.5,-100)
  Bottom Layer w10: R538E.2@-2137.5,-133.46 v1(-2137.5,-100)
NetR116F_1: R116F.1 R538F.2 U19F.1 | length 136.6
  Top Layer w10: U19F.1@-2205.81,-588.39 -2149.38,-588.39 ccw(c-2149.38,-571.58) R116F.1@-2137.5,-583.46 v1(-2137.5,-550)
  Bottom Layer w10: R538F.2@-2137.5,-583.46 v1(-2137.5,-550)
NetR116G_1: R116G.1 R538G.2 U19G.1 | length 136.6
  Top Layer w10: U19G.1@-2205.81,-1038.39 -2149.38,-1038.39 ccw(c-2149.38,-1021.58) R116G.1@-2137.5,-1033.46 v1(-2137.5,-1000)
  Bottom Layer w10: R538G.2@-2137.5,-1033.46 v1(-2137.5,-1000)
NetR116H_1: R116H.1 R538H.2 U19H.1 | length 136.6
  Top Layer w10: U19H.1@-2205.81,-1488.39 -2149.38,-1488.39 ccw(c-2149.38,-1471.58) R116H.1@-2137.5,-1483.46 v1(-2137.5,-1450)
  Bottom Layer w10: R538H.2@-2137.5,-1483.46 v1(-2137.5,-1450)
NetR124A_1: R124A.1 R537A.2 U18A.1 | length 136.6
  Top Layer w10: U18A.1@-2205.81,1449.11 -2149.38,1449.11 ccw(c-2149.38,1465.92) R124A.1@-2137.5,1454.04 v1(-2137.5,1487.5)
  Bottom Layer w10: R537A.2@-2137.5,1454.04 v1(-2137.5,1487.5)
NetR124B_1: R124B.1 R537B.2 U18B.1 | length 136.6
  Top Layer w10: U18B.1@-2205.81,999.11 -2149.38,999.11 ccw(c-2149.38,1015.92) R124B.1@-2137.5,1004.04 v1(-2137.5,1037.5)
  Bottom Layer w10: R537B.2@-2137.5,1004.04 v1(-2137.5,1037.5)
NetR124C_1: R124C.1 R537C.2 U18C.1 | length 136.6
  Top Layer w10: U18C.1@-2205.81,549.11 -2149.38,549.11 ccw(c-2149.38,565.92) R124C.1@-2137.5,554.04 v1(-2137.5,587.5)
  Bottom Layer w10: R537C.2@-2137.5,554.04 v1(-2137.5,587.5)
NetR124D_1: R124D.1 R537D.2 U18D.1 | length 136.6
  Top Layer w10: U18D.1@-2205.81,99.11 -2149.38,99.11 ccw(c-2149.38,115.92) R124D.1@-2137.5,104.04 v1(-2137.5,137.5)
  Bottom Layer w10: R537D.2@-2137.5,104.04 v1(-2137.5,137.5)
NetR124E_1: R124E.1 R537E.2 U18E.1 | length 136.6
  Top Layer w10: U18E.1@-2205.81,-350.89 -2149.38,-350.89 ccw(c-2149.38,-334.08) R124E.1@-2137.5,-345.96 v1(-2137.5,-312.5)
  Bottom Layer w10: R537E.2@-2137.5,-345.96 v1(-2137.5,-312.5)
NetR124F_1: R124F.1 R537F.2 U18F.1 | length 136.6
  Top Layer w10: U18F.1@-2205.81,-800.89 -2149.38,-800.89 ccw(c-2149.38,-784.08) R124F.1@-2137.5,-795.96 v1(-2137.5,-762.5)
  Bottom Layer w10: R537F.2@-2137.5,-795.96 v1(-2137.5,-762.5)
NetR124G_1: R124G.1 R537G.2 U18G.1 | length 136.6
  Top Layer w10: U18G.1@-2205.81,-1250.89 -2149.38,-1250.89 ccw(c-2149.38,-1234.08) R124G.1@-2137.5,-1245.96 v1(-2137.5,-1212.5)
  Bottom Layer w10: R537G.2@-2137.5,-1245.96 v1(-2137.5,-1212.5)
NetR124H_1: R124H.1 R537H.2 U18H.1 | length 136.6
  Top Layer w10: U18H.1@-2205.81,-1700.89 -2149.38,-1700.89 ccw(c-2149.38,-1684.08) R124H.1@-2137.5,-1695.96 v1(-2137.5,-1662.5)
  Bottom Layer w10: R537H.2@-2137.5,-1695.96 v1(-2137.5,-1662.5)
NetR132_1: R132.1 U100.1 | length 132.2
  Top Layer w10: R132.1@-1362.5,-13.09 -1340.02,-35.57 ccw(c-1280,24.44) v1(-1280,-60.43)
  Bottom Layer w10: U100.1@-1313.78,-60.43 v1(-1280,-60.43)
NetR132_2: R132.2 U42.5 | length 83.1
  Top Layer w10: U42.5@-1415.65,100.1 -1368.76,53.21 cw(c-1383.89,38.09) R132.2@-1362.5,38.09
NetR133_1: R133.1 R141.1 U43.1 U44.7 | length 344
  Top Layer w15: R141.1@-913.09,662.5 -912.5,662.5 U43.1@-912.5,756.4 -912.5,763.09 ccw(c-987.5,763.09) R133.1@-987.5,838.09 -928.68,896.91 cw(c-891.04,859.28) U44.7@-891.04,912.5
NetR134_1: R134.1 R147.1 U43.15 U44.5 | length 400.1
  Top Layer w15: R134.1@-987.5,963.09 cw(c-938.09,963.09) -938.09,1012.5 U44.5@-891.04,1012.5 ccw(c-891.04,1041.04) -862.5,1041.04 U43.15@-862.5,1118.6 cw(c-768.6,1118.6) -768.6,1212.5 R147.1@-763.09,1212.5
NetR146_1: R146.1 U43.3 | length 122.1
  Top Layer w15: U43.3@-812.5,756.4 -812.5,711.91 ccw(c-763.09,711.91) R146.1@-763.09,662.5
NetR154_1: R154.1 R160.1 U43.9 U44.3 | length 344
  Top Layer w15: U44.3@-583.96,962.5 ccw(c-583.96,1015.72) -546.32,978.09 R160.1@-487.5,1036.91 cw(c-487.5,1111.91) -562.5,1111.91 U43.9@-562.5,1118.6 -562.5,1212.5 R154.1@-561.91,1212.5
NetR158_1: R158.1 R159.1 U43.8 U44.2 | length 295
  Top Layer w15: U44.2@-583.96,912.5 -488.09,912.5 R159.1@-487.5,911.91 R158.1@-487.5,838.09 ccw(c-487.5,763.09) -562.5,763.09 U43.8@-562.5,756.4
NetR161_2: R161.2 R165.2 U49.2 | length 257.6
  Top Layer w20: v2(-345,-1587.5) -345,-1493.77 cw(c-340.73,-1493.77) U49.2@-343.75,-1490.75
  Bottom Layer w10: v2(-345,-1587.5) -345,-1540 -359.19,-1525.81 -359.97,-1525.81 -368.75,-1517.03 -368.75,-1509.15 -359.97,-1500.37 -357.21,-1500.37 -331.47,-1474.63 -327.53,-1474.63 -318.75,-1465.85 R161.2@-318.75,-1461.91
NetR168_1: R168.1 R364.2 U59.6 | length 440.6
  Top Layer w10: R168.1@-36.91,-1662.5 -36.91,-1617.14 cw(c17.73,-1617.14) 17.73,-1562.5 37.5,-1562.5 cw(c37.5,-1612.5) 87.5,-1612.5 U59.6@87.5,-1656.99 v2(87.5,-1702.5)
  Bottom Layer w10: v2(87.5,-1702.5) 87.5,-1648.45 cw(c172.86,-1648.45) R364.2@112.5,-1588.09
NetR170_1: R170.1 U54.9 U55.1 | length 414.7
  Top Layer w10: U54.9@9.25,798.82 -21.62,798.82 cw(c-21.62,862.2) -85,862.2 -85,1011.95 cw(c-46.85,1011.95) U55.1@-46.85,1050.1 -5.53,1050.1 ccw(c-5.53,1092.44) R170.1@24.41,1062.5
NetR171_1: R171.1 U54.5 U55.2 | length 446.8
  Top Layer w10: U54.5@-209.25,824.41 -178.86,824.41 ccw(c-178.86,888.27) -115,888.27 -115,1019.35 cw(c-46.85,1019.35) U55.2@-46.85,1087.5 -35.95,1087.5 ccw(c-35.95,1172.86) R171.1@24.41,1112.5
NetR172_1: R172.1 U58.9 U60.2 | length 692.4
  Top Layer w10: U58.9@3.25,-911.32 -36.32,-911.32 ccw(c-36.32,-937.5) -62.5,-937.5 -62.5,-1137.5 ; R172.1@37.5,-1236.91 -25.59,-1236.91 cw(c-25.59,-1200) -62.5,-1200 -62.5,-1137.5 ; U60.2@165.65,-1137.5 -62.5,-1137.5
NetR176_1: R176.1 U58.5 U60.1 | length 466.1
  Top Layer w10: U60.1@165.65,-1174.9 U60.1@187.5,-1174.9 ; R176.1@187.5,-1236.91 U60.1@187.5,-1174.9 ; U58.5@221.75,-936.91 261.91,-936.91 cw(c261.91,-962.5) 287.5,-962.5 287.5,-1150 cw(c262.5,-1150) 262.5,-1175 262.5,-1174.9 U60.1@187.5,-1174.9
NetR196_1: R196.1 U72.6 | length 38
  Top Layer w10: v1(1250.3,848.33) 1250.3,832.22 ccw(c1278.19,832.22) R196.1@1258.46,812.5
NetR197_2: R197.2 R205.1 U72.5 | length 150.6
  Bottom Layer w15: U72.5@1275.89,874.9 ccw(c1275.89,917.77) 1318.75,917.77 R205.1@1318.75,936.91 1375,936.91 R197.2@1375,929.04
NetR198_1: R198.1 R199.1 R204.2 R207.1 | length 193.6
  Top Layer w10: R207.1@1187.5,-1516.54 1197.58,-1506.46 ccw(c1141.12,-1450) R204.2@1220.96,-1450 ; R204.2@1220.96,-1441.65 R198.1@1220.96,-1387.5 R199.1@1220.96,-1325
NetR201_1: R201.1 R202.2 R203.1 | length 183.3
  Top Layer w10: R202.2@1154.04,-1137.5 cw(c1154.04,-1142.85) R202.2@1157.82,-1139.07 ; R201.1@1220.96,-1200 cw(c1220.96,-1194.65) 1217.19,-1198.44 R202.2@1157.82,-1139.07 ; R203.1@1220.96,-1075 ccw(c1220.96,-1080.35) 1217.19,-1076.56 1160.03,-1133.72 ccw(c1165.38,-1139.07) R202.2@1157.82,-1139.07
NetR206_1: R206.1 R209.2 U73.5 | length 170
  Bottom Layer w10: U73.5@1275.89,1344.05 U73.5@1275.89,1324.9 1275.89,1280.8 ccw(c1301.76,1280.8) R209.2@1283.46,1262.5
  Bottom Layer w15: U73.5@1275.89,1324.9 ccw(c1275.89,1367.77) 1318.75,1367.77 R206.1@1318.75,1386.91
NetR208_1: R208.1 U73.6 | length 64.6
  Top Layer w10: v1(1250.3,1297.82) 1250.3,1282.22 ccw(c1278.19,1282.22) R208.1@1258.46,1262.5
  Bottom Layer w10: v1(1250.3,1297.82) U73.6@1250.3,1324.9
NetR212_2: R212.2 U76.2 | length 145.5
  Top Layer w20: R212.2@1262.5,-1516.54 ccw(c1262.5,-1465.92) 1298.29,-1501.71 v4(1325,-1475) U76.2@1325,-1406.99
NetR213_1: R213.1 U72.8 | length 87.2
  Bottom Layer w15: R213.1@1150,929.04 1150,924.02 ccw(c1199.11,924.02) U72.8@1199.11,874.9 U72.8@1199.11,879.92
NetR213_2: R213.2 U72.1 | length 82.2
  Bottom Layer w15: R213.2@1150,995.96 1150,1000.98 cw(c1199.11,1000.98) U72.1@1199.11,1050.1
NetR214_1: R214.1 U73.8 | length 82.2
  Bottom Layer w15: R214.1@1150,1379.04 1150,1374.02 ccw(c1199.11,1374.02) U73.8@1199.11,1324.9
NetR214_2: R214.2 U73.1 | length 82.2
  Bottom Layer w15: R214.2@1150,1445.96 1150,1450.98 cw(c1199.11,1450.98) U73.1@1199.11,1500.1
NetR215_1: R215.1 R343.1 U77.6 | length 112.6
  Top Layer w7: R215.1@1520,1383.46 1524.26,1379.2 ccw(c1571,1425.94) v1(1571,1359.84)
  Top Layer w10: v1(1571,1359.84) U77.6@1590.16,1359.84
  Bottom Layer w7: R343.1@1538.09,1350 cw(c1561.85,1326.24) 1561.85,1359.84 v1(1571,1359.84)
NetR216_2: R216.2 U77.15 | length 58.1
  Top Layer w7: R216.2@1637.5,1163.09 cw(c1675.33,1163.09) 1648.58,1189.84 v1(1656.1,1197.36)
  Top Layer w10: v1(1656.1,1197.36) U77.15@1656.1,1215.16
NetR217_2: R217.2 U77.46 | length 58.3
  Top Layer w7: R217.2@1637.5,1536.91 ccw(c1671.95,1536.91) 1647.59,1512.55 v1(1656.1,1504.04)
  Top Layer w10: U77.46@1656.1,1484.84 v1(1656.1,1504.04)
NetR218_1: R218.1 R219.1 U77.45 | length 229.1
  Top Layer w7: R219.1@1649.41,1637.5 ccw(c1649.41,1640.35) 1651.42,1638.33 R218.1@1700.59,1687.5 ; R219.1@1662.5,1637.5 1662.5,1525 ccw(c1681.03,1525) 1667.93,1511.89 v1(1675.79,1504.04)
  Top Layer w10: U77.45@1675.79,1484.84 v1(1675.79,1504.04)
NetR220_1: R220.1 R221.2 U85.7 | length 493.7
  Top Layer w10: v4(2037.5,-348.52) U85.7@2079.44,-348.52
  Top Layer w15: R220.1@1674.41,-350 1691.58,-332.83 ccw(c1671.25,-312.5) v2(1700,-312.5) cw(c1728.75,-312.5) 1708.42,-292.17 R221.2@1725.59,-275
  Bottom Layer w15: v2(1700,-312.5) 2001.48,-312.5 cw(c2001.48,-348.52) v4(2037.5,-348.52)
NetR222_1: R222.1 R223.2 U87.7 | length 493.7
  Top Layer w10: v4(2037.5,51.48) U87.7@2079.44,51.48
  Top Layer w15: R222.1@1674.41,50 1691.58,67.17 ccw(c1671.25,87.5) v2(1700,87.5) cw(c1728.75,87.5) 1708.42,107.83 R223.2@1725.59,125
  Bottom Layer w15: v2(1700,87.5) 2001.48,87.5 cw(c2001.48,51.48) v4(2037.5,51.48)
NetR224_1: R224.1 R336.1 U77.16 | length 87
  Top Layer w7: R224.1@1675,1163.09 1675,1214.37 cw(c1675.79,1214.37) U77.16@1675.79,1215.16
  Bottom Layer w7: R336.1@1675,1163.09 ccw(c1673.1,1164.99) 1675.79,1164.99 v1(1675.79,1197.36)
NetR225_1: R225.1 R226.1 U77.40 | length 229.1
  Top Layer w7: R226.1@1749.41,1687.5 1798.57,1638.34 ccw(c1800.59,1640.35) R225.1@1800.59,1637.5 ; v1(1774.21,1504.04) 1782.07,1511.89 ccw(c1768.97,1525) 1787.5,1525 R225.1@1787.5,1637.5
  Top Layer w10: U77.40@1774.21,1484.84 v1(1774.21,1504.04)
NetR227_1: R227.1 U77.41 | length 54.2
  Top Layer w7: v1(1754.53,1504.04) 1754.53,1517.66 cw(c1781.75,1517.66) R227.1@1762.5,1536.91
  Top Layer w10: U77.41@1754.53,1484.84 v1(1754.53,1504.04)
NetR228_1: R228.1 R329.1 U77.21 | length 87
  Top Layer w7: U77.21@1774.21,1215.16 cw(c1774.21,1214.37) 1775,1214.37 R228.1@1775,1163.09
  Bottom Layer w7: v1(1774.21,1197.36) 1774.21,1164.99 ccw(c1776.9,1164.99) R329.1@1775,1163.09
NetR229_2: R229.2 U77.22 | length 58.1
  Top Layer w7: v1(1793.9,1197.36) 1801.42,1189.84 cw(c1774.67,1163.09) R229.2@1812.5,1163.09
  Top Layer w10: v1(1793.9,1197.36) U77.22@1793.9,1215.16
NetR230_2: R230.2 U77.39 | length 58.3
  Top Layer w7: v1(1793.9,1504.04) 1802.41,1512.55 ; 1802.42,1512.56 ccw(c1778.05,1536.91) R230.2@1812.5,1536.91
  Top Layer w10: U77.39@1793.9,1484.84 v1(1793.9,1504.04)
NetR233_1: R233.1 U78.6 | length 42.7
  Top Layer w10: R233.1@2006.25,1667.79 2006.25,1674.7 v1(2042.08,1674.7)
NetR234_1: R234.1 R241.2 U83.7 | length 129.7
  Top Layer w16: R234.1@1950,-749.41 cw(c1952.14,-751.55) 1952.14,-748.52 U83.7@2079.44,-748.52
NetR235_1: R235.1 R242.2 U84.7 | length 129.7
  Top Layer w16: R235.1@1950,-549.41 cw(c1952.14,-551.55) 1952.14,-548.52 U84.7@2079.44,-548.52
NetR236_2: R236.2 U79.10 U79.11 U79.12 | length 214.4
  Top Layer w16: R236.2@1987.5,-1645.96 ccw(c1992.42,-1645.96) 1992.42,-1650.89 v4(2045.19,-1650.89) ; U79.12@2079.44,-1676.48 v4(2045.19,-1676.48) v4(2045.19,-1650.89) ; U79.11@2079.44,-1650.89 v4(2045.19,-1650.89) ; U79.10@2079.44,-1625.3 v4(2045.19,-1625.3) v4(2045.19,-1650.89)
NetR237_2: R237.2 R306.1 U80.10 U80.11 U80.12 | length 366.4
  Top Layer w16: R237.2@1987.5,-1445.96 ccw(c1992.42,-1445.96) 1992.42,-1450.89 v4(2045.19,-1450.89) ; U80.12@2079.44,-1476.48 v4(2045.19,-1476.48) v4(2045.19,-1450.89) ; U80.11@2079.44,-1450.89 v4(2045.19,-1450.89) ; U80.10@2079.44,-1425.3 v4(2045.19,-1425.3) v4(2045.19,-1450.89)
  Bottom Layer w16: v4(2045.19,-1425.3) v4(2045.19,-1450.89) v4(2045.19,-1476.48) ccw(c2061.22,-1476.48) 2061.22,-1492.5 R306.1@2136.91,-1492.5
NetR238_2: R238.2 U81.10 U81.11 U81.12 | length 214.4
  Top Layer w16: R238.2@1987.5,-1245.96 ccw(c1992.42,-1245.96) 1992.42,-1250.89 v4(2045.19,-1250.89) ; U81.12@2079.44,-1276.48 v4(2045.19,-1276.48) v4(2045.19,-1250.89) ; U81.11@2079.44,-1250.89 v4(2045.19,-1250.89) ; U81.10@2079.44,-1225.3 v4(2045.19,-1225.3) v4(2045.19,-1250.89)
NetR239_2: R239.2 R311.1 U82.10 U82.11 U82.12 | length 302.4
  Top Layer w16: R239.2@1987.5,-1045.96 ccw(c1992.42,-1045.96) 1992.42,-1050.89 v4(2045.19,-1050.89) ; U82.12@2079.44,-1076.48 v4(2045.19,-1076.48) v4(2045.19,-1050.89) ; U82.11@2079.44,-1050.89 v4(2045.19,-1050.89) ; U82.10@2079.44,-1025.3 v4(2045.19,-1025.3) v4(2045.19,-1050.89)
  Bottom Layer w16: v4(2045.19,-1076.48) v4(2045.19,-1050.89) v4(2045.19,-1025.3) 2062.8,-1025.3 ccw(c2062.8,-1013.09) R311.1@2075,-1013.09
NetR240_2: R240.2 R246.1 U78.5 | length 156.5
  Bottom Layer w15: R240.2@2006.25,1641.54 2006.25,1649.11 v1(2042.08,1649.11) U78.5@2068.65,1649.11 ccw(c2111.52,1649.11) 2111.52,1606.25 R246.1@2130.66,1606.25
NetR244_1: R244.1 R299.1 U79.1 U79.2 U79.3 U79.5 U79.13 U80.1 U80.2 U80.3 U80.13 | length 1032.5
  Top Layer w15: v4(2162.5,-1562.5) ccw(c2174.11,-1562.5) 2174.11,-1574.11 U79.5@2245.56,-1574.11
  Top Layer w16: R244.1@2119.34,-1512.5 2137.5,-1512.5 ; v4(2137.5,-1562.2) 2137.5,-1512.5 ; v4(2137.5,-1462.5) 2137.5,-1512.5 ; v4(2162.5,-1662.5) 2162.5,-1650.89 U79.2@2245.56,-1650.89 ; v11(2162.5,-1612.5) 2162.5,-1625.3 U79.3@2245.56,-1625.3 U79.2@2245.56,-1650.89 ; v4(2162.5,-1562.5) v4(2162.5,-1462.5) 2162.5,-1450.89 U80.2@2245.56,-1450.89 ; v11(2162.5,-1412.5) 2162.5,-1425.3 U80.3@2245.56,-1425.3 U80.2@2245.56,-1450.89 ; U79.1@2245.56,-1676.48 U79.2@2245.56,-1650.89 ; U80.1@2245.56,-1476.48 U80.2@2245.56,-1450.89
  Bottom Layer w35: v11(2162.5,-1612.5) R299.1@2404.04,-1612.5
  other v4: 2137.5,-1662.5 2187.5,-1662.5 2137.5,-1637.5 2187.5,-1637.5 2137.5,-1587.5 2187.5,-1587.5 2187.5,-1562.5 2187.5,-1462.5 2137.5,-1437.5 2187.5,-1437.5 2137.5,-1387.5 2187.5,-1387.5 2137.5,-1362.2 2162.5,-1362.5 2187.5,-1362.5
NetR245_1: R245.1 U78.8 | length 82.2
  Bottom Layer w15: U78.8@2068.65,1725.89 cw(c2117.77,1725.89) 2117.77,1775 R245.1@2122.79,1775
NetR245_2: R245.2 U78.1 | length 82.2
  Bottom Layer w15: R245.2@2189.71,1775 2194.73,1775 cw(c2194.73,1725.89) U78.1@2243.85,1725.89
NetR251_2: R251.2 R300.1 U81.1 U81.2 U81.4 U81.7 U82.1 U82.2 U82.4 | length 900.1
  Top Layer w15: U81.7@2079.44,-1148.52 2085.06,-1148.52 ccw(c2085.06,-1048.52) 2155.77,-1119.23 2169.23,-1105.77 cw(c2239.95,-1176.48) 2239.95,-1076.48 U82.1@2245.56,-1076.48 ; U82.2@2245.56,-1050.89 U82.1@2245.56,-1076.48 ; 2312.5,-1076.48 U82.1@2245.56,-1076.48
  Top Layer w16: R251.2@2188.09,-1312.5 2209.54,-1312.5 ccw(c2209.54,-1276.48) U81.1@2245.56,-1276.48 U81.2@2245.56,-1250.89 2281.54,-1250.89 ccw(c2281.54,-1219.92) 2312.5,-1219.92 2312.5,-1199.7 ; U81.4@2245.56,-1199.7 2312.5,-1199.7 ; U82.4@2245.56,-999.7 2280.81,-999.7 cw(c2280.81,-1031.4) 2312.5,-1031.4 2312.5,-1076.48 v8(2312.5,-1112.5) 2312.5,-1199.7
  Bottom Layer w35: v8(2312.5,-1112.5) R300.1@2404.04,-1112.5
NetR255_1: R255.1 U92.8 | length 81.9
  Bottom Layer w15: R255.1@2189.71,875 2194.46,875 ccw(c2194.46,924.11) U92.8@2243.57,924.11
NetR255_2: R255.2 U92.1 | length 82.4
  Bottom Layer w15: U92.1@2068.38,924.11 ccw(c2117.49,924.11) 2117.49,875 R255.2@2122.79,875
NetR256_1: R256.1 R267.2 U92.5 | length 162.7
  Bottom Layer w15: R256.1@2181.84,1043.75 2200.71,1043.75 cw(c2200.71,1000.89) U92.5@2243.57,1000.89 2312.5,1000.89 R267.2@2312.5,1008.46
NetR261_1: R261.1 U85.1 U85.2 U85.4 | length 198.1
  Top Layer w15: U85.1@2245.56,-476.48 U85.2@2245.56,-450.89 2262.51,-450.89 ccw(c2262.51,-362.51) 2325,-425 ccw(c2263.93,-486.07) 2263.93,-399.7 U85.4@2245.56,-399.7
NetR262_1: R262.1 U86.1 U86.2 U86.4 U86.7 | length 531.3
  Top Layer w15: U86.7@2079.44,-148.52 cw(c2136.23,-205.31) 2136.23,-125 2281.54,-125 cw(c2281.54,-168.46) 2325,-168.46 R262.1@2325,-225 ; U86.1@2245.56,-276.48 U86.2@2245.56,-250.89 2262.51,-250.89 ccw(c2262.51,-162.51) R262.1@2325,-225 ; U86.4@2245.56,-199.7 2263.93,-199.7 cw(c2263.93,-286.07) R262.1@2325,-225
NetR263_1: R263.1 U87.1 U87.2 U87.4 | length 198.1
  Top Layer w15: U87.1@2245.56,-76.48 U87.2@2245.56,-50.89 2262.51,-50.89 ccw(c2262.51,37.49) 2325,-25 ccw(c2263.93,-86.07) 2263.93,0.3 U87.4@2245.56,0.3
NetR264_1: R264.1 U88.1 U88.2 U88.4 U88.7 | length 530.3
  Top Layer w15: U88.7@2079.44,251.48 cw(c2136.23,194.69) 2136.23,275 2279.04,275 cw(c2279.04,229.04) 2325,229.04 R264.1@2325,175 ; U88.1@2245.56,123.52 U88.2@2245.56,149.11 2262.51,149.11 ccw(c2262.51,237.49) R264.1@2325,175 ; U88.4@2245.56,200.3 2263.93,200.3 cw(c2263.93,113.93) R264.1@2325,175
NetR265_1: R265.1 U89.1 U89.2 U89.4 | length 198.8
  Top Layer w15: U89.1@2245.56,323.52 U89.2@2245.56,349.11 2282.94,349.11 ccw(c2282.94,408.59) 2325,366.54 ccw(c2249.95,300.41) U89.4@2245.69,400.35
NetR266_1: R266.1 U90.1 U90.2 U90.4 | length 212.8
  Top Layer w15: U90.1@2245.56,523.52 U90.2@2245.56,549.11 U90.2@2249.23,549.11 ; U90.4@2245.56,600.3 2284.37,600.3 cw(c2284.37,542.83) 2325,583.46 2319.94,578.4 cw(c2249.23,649.11) U90.2@2249.23,549.11 ; U90.2@2263.12,549.11 U90.2@2249.23,549.11
NetR268_1: R268.1 U92.6 | length 55.1
  Top Layer w10: v1(2270.15,975.3) ccw(c2270.15,997.47) 2285.82,981.79 R268.1@2312.5,1008.46
NetR269_1: R269.1 U94.3 | length 56.1
  Top Layer w10: U94.3@2512.5,1631.99 R269.1@2512.5,1688.06
NetR270_2: R270.2 U94.5 | length 56.1
  Top Layer w10: R270.2@2462.5,1386.94 U94.5@2462.5,1443.01
NetR273_2: R273.2 R279.1 U80.7 | length 970
  Top Layer w15: v4(2045.19,-1348.52) U80.7@2079.44,-1348.52 ; R273.2@2568.75,-1199.41 cw(c2600.66,-1199.41) 2600.66,-1167.5 v1(2718.75,-1167.5) R279.1@2750.66,-1167.5
  Int5 (ST) w15: v4(2045.19,-1348.52) 2051.93,-1341.79 cw(c2122.64,-1412.5) 2122.64,-1312.5 2465.12,-1312.5 ccw(c2465.12,-1212.5) 2535.83,-1283.21 2622.26,-1196.79 cw(c2692.97,-1267.5) 2692.97,-1167.5 v1(2718.75,-1167.5)
NetR274_1: R274.1 R280.1 U81.3 | length 703.1
  Top Layer w15: U81.3@2245.56,-1225.3 v4(2284.43,-1225.3) ; R274.1@2568.75,-1100.59 ccw(c2600.66,-1100.59) 2600.66,-1132.5 v1(2718.75,-1132.5) R280.1@2750.66,-1132.5
  Int5 (ST) w15: v4(2284.43,-1225.3) 2465.38,-1225.3 ccw(c2465.38,-1125.3) 2536.09,-1196.01 2570.3,-1161.79 cw(c2641.01,-1232.5) 2641.01,-1132.5 v1(2718.75,-1132.5)
NetR275_2: R275.2 R282.1 | length 207.7
  Top Layer w10: R275.2@2568.75,88.09 cw(c2608.32,88.09) 2608.32,127.66 2743,127.66 R282.1@2750.66,120
NetR276_1: R276.1 R283.1 | length 207.7
  Top Layer w10: R276.1@2568.75,186.91 ccw(c2608.32,186.91) 2608.32,147.34 2743,147.34 R283.1@2750.66,155
NetR279_2: R279.2 U95.7 | length 94.8
  Top Layer w10: R279.2@2801.84,-1167.5 cw(c2809.5,-1167.5) 2809.5,-1159.84 U95.7@2892.25,-1159.84
NetR280_2: R280.2 U95.6 | length 94.8
  Top Layer w10: R280.2@2801.84,-1132.5 ccw(c2809.5,-1132.5) 2809.5,-1140.16 U95.6@2892.25,-1140.16
NetR282_2: R282.2 U96.7 | length 93.6
  Top Layer w10: R282.2@2801.84,120 2809.5,127.66 U96.7@2892.25,127.66
NetR283_2: R283.2 U96.6 | length 93.6
  Top Layer w10: R283.2@2801.84,155 2809.5,147.34 U96.6@2892.25,147.34
NetR285_2: R285.2 U95.21 | length 78.8
  Top Layer w10: U95.21@3045.25,-1100.79 3115.22,-1100.79 ccw(c3115.22,-1089.56) R285.2@3123.16,-1097.5
NetR286_2: R286.2 U96.21 | length 78.8
  Top Layer w10: U96.21@3045.25,186.71 3115.22,186.71 ccw(c3115.22,197.94) R286.2@3123.16,190
NetR287_1: R287.1 U95.15 | length 84.1
  Top Layer w10: U95.15@3045.25,-1218.9 3066.52,-1218.9 cw(c3066.52,-1239.73) 3081.25,-1225 3089.79,-1233.54 ccw(c3099.36,-1223.96) 3099.36,-1237.5 R287.1@3123.16,-1237.5
NetR288_1: R288.1 U95.16 | length 78.8
  Top Layer w10: U95.16@3045.25,-1199.21 3115.22,-1199.21 cw(c3115.22,-1210.44) R288.1@3123.16,-1202.5
NetR289_1: R289.1 U95.22 | length 84.1
  Top Layer w10: U95.22@3045.25,-1081.1 3066.52,-1081.1 ccw(c3066.52,-1060.27) 3081.25,-1075 3089.79,-1066.46 cw(c3099.36,-1076.04) 3099.36,-1062.5 R289.1@3123.16,-1062.5
NetR290_1: R290.1 U96.15 | length 84.1
  Top Layer w10: U96.15@3045.25,68.6 3066.52,68.6 cw(c3066.52,47.77) 3081.25,62.5 3089.79,53.96 ccw(c3099.36,63.54) 3099.36,50 R290.1@3123.16,50
NetR291_1: R291.1 U96.16 | length 78.8
  Top Layer w10: U96.16@3045.25,88.29 3115.22,88.29 cw(c3115.22,77.06) R291.1@3123.16,85
NetR292_1: R292.1 U96.22 | length 84.1
  Top Layer w10: U96.22@3045.25,206.4 3066.52,206.4 ccw(c3066.52,227.23) 3081.25,212.5 3089.79,221.04 cw(c3099.36,211.46) 3099.36,225 R292.1@3123.16,225
NetR303_2: R303.2 R304.1 R308.1 | length 125
  Bottom Layer w25: R308.1@2125,1479.04 R304.1@2187.5,1479.04 R303.2@2250,1479.04
NetR305_1: R305.1 R306.2 U80.5 | length 279
  Top Layer w16: U80.5@2245.56,-1374.11 v4(2281.25,-1374.11)
  Bottom Layer w12: R305.1@2136.91,-1532.5 2142.5,-1532.5 2182.5,-1492.5 R306.2@2188.09,-1492.5
  Bottom Layer w16: R306.2@2188.09,-1492.5 2195.59,-1492.5 ccw(c2195.59,-1443.21) 2244.88,-1443.21 2244.88,-1408.55 cw(c2279.31,-1408.55) 2279.31,-1374.11 v4(2281.25,-1374.11)
NetR307_1: R307.1 R311.2 U82.7 | length 130.2
  Top Layer w16: v4(2045.19,-948.52) U82.7@2079.44,-948.52
  Bottom Layer w16: v4(2045.19,-948.52) 2098.23,-948.52 ccw(c2098.23,-893.82) R307.1@2136.91,-932.5
NetR316_1: R316.1 R318.2 U89.7 | length 129.9
  Top Layer w15: R318.2@1950,450.59 cw(c1950.89,450.59) 1950.89,451.48 v4(2037.5,451.48) U89.7@2079.44,451.48
NetR317_1: R317.1 R319.2 U90.7 | length 129.9
  Top Layer w15: R319.2@1950,650.59 cw(c1950.89,650.59) 1950.89,651.48 v4(2038.19,651.48) U90.7@2079.44,651.48
NetR324_2: R324.2 R328.1 U77.38 | length 89.9
  Top Layer w10: U77.38@1813.58,1484.84 v1(1813.58,1504.04)
  Bottom Layer w10: v1(1813.58,1504.04) 1813.58,1534.3 ccw(c1809.89,1534.3) R328.1@1812.5,1536.91 R324.2@1850,1536.91
NetR330_1: R330.1 R331.1 R335.1 U77.43 | length 177.7
  Top Layer w10: U77.43@1715.16,1484.84 v1(1715.16,1504.04)
  Bottom Layer w7: R335.1@1687.5,1588.09 ccw(c1698.69,1588.09) 1690.78,1580.18 1718.6,1552.35 cw(c1703.16,1536.91) R331.1@1725,1536.91 ; v1(1715.16,1504.04) 1715.16,1536.91 R331.1@1725,1536.91 ; R331.1@1720.15,1548.61 cw(c1708.46,1536.91) R331.1@1725,1536.91 ; R330.1@1762.5,1536.91 R331.1@1725,1536.91
NetR337_1: R337.1 R339.2 U77.14 | length 90.2
  Top Layer w10: v1(1636.42,1197.36) U77.14@1636.42,1215.16
  Bottom Layer w7: v1(1636.42,1197.36) 1636.42,1164.17 ccw(c1637.5,1164.17) R337.1@1637.5,1163.09
  Bottom Layer w10: R339.2@1600,1163.09 R337.1@1637.5,1163.09
NetR338_1: R338.1 R340.2 U77.47 | length 89.9
  Top Layer w10: U77.47@1636.42,1484.84 v1(1636.42,1504.04)
  Bottom Layer w7: R340.2@1600,1536.91 R338.1@1637.5,1536.91 ccw(c1640.11,1534.3) 1636.42,1534.3 v1(1636.42,1504.04)
NetR341_2: R341.2 R344.1 U77.37 | length 373.7
  Top Layer w7: U77.37@1833.27,1484.84 v1(1833.27,1504.04)
  Bottom Layer w7: R344.1@1525,1536.91 R341.2@1562.5,1536.91 1562.5,1517.5 ccw(c1592.69,1517.5) 1592.69,1487.3 1816.54,1487.3 ccw(c1816.54,1504.04) v1(1833.27,1504.04)
NetR342_2: R342.2 R345.1 U77.5 U77.48 | length 370.8
  Top Layer w10: v1(1571,1379.53) U77.5@1590.16,1379.53 ; U77.48@1616.73,1484.84 v1(1616.73,1504.04)
  Int5 (ST) w7: v1(1571,1379.53) 1579.53,1379.53 ccw(c1579.53,1400) 1600,1400 1600,1487.3 cw(c1616.73,1487.3) v1(1616.73,1504.04)
  Bottom Layer w7: R345.1@1425,1375.59 cw(c1461.91,1375.59) 1461.91,1412.5 1500,1412.5 cw(c1500,1380.9) 1522.35,1403.24 1538.09,1387.5 ccw(c1557.34,1406.75) 1557.34,1379.53 v1(1571,1379.53)
NetR355_1: R355.1 R358.2 U98.6 | length 287.7
  Int6 (SB) w15: v4(412.5,962.5) v4(517.5,1075)
  Bottom Layer w14: U98.6@456.99,1112.5 cw(c456.99,1056.94) 496.27,1096.23 v4(517.5,1075) ccw(c547.68,1105.18) 547.68,1062.5 R355.1@549.41,1062.5
  Bottom Layer w15: R358.2@387.63,962.5 v4(412.5,962.5)
NetR357_1: R357.1 U50.F8 | length 476.7
  Top Layer w10: U50.F8@137.8,-216.54 v3(157.48,-236.22)
  Bottom Layer w4.21: v3(157.48,-236.22) cw(c177.17,-236.22) 177.17,-216.54 338.58,-216.66 401.57,-216.66 ccw(c401.57,-208.66) 401.67,-216.66 411.69,-216.54 ; 411.81,-216.54 ccw(c411.81,-226.54) 411.69,-216.54 ; R357.1@500,-349.41 500,-304.85 ccw(c411.69,-304.85) 411.69,-216.54
NetR368_1: R368.1 R370.1 U51.2 | length 37.5
  Bottom Layer w10: R370.1@-74.41,1187.5 R368.1@-74.41,1225
  other v4: -74.41,1206.25
NetR395_2: R395.2 R396.2 R397.1 U99.4 | length 181.9
  Bottom Layer w15: R396.2@-1036.91,-1525 R397.1@-1036.91,-1475 ccw(c-1036.91,-1463.19) -1025.1,-1463.19 U99.4@-1025.1,-1403.15 cw(c-997.54,-1403.15) -997.54,-1375.59 R395.2@-987.5,-1375.59
NetR402A_2: R402A.2 R418A.2 U34A.5 | length 68.6
  Top Layer w5: U34A.5@-1670.38,1600.79 v1(-1639.57,1600.79)
  Bottom Layer w5: R418A.2@-1658.44,1600.79 v1(-1639.57,1600.79) R402A.2@-1620.69,1600.79
NetR402B_2: R402B.2 R418B.2 U34B.5 | length 68.6
  Top Layer w5: U34B.5@-1670.38,1150.79 v1(-1639.57,1150.79)
  Bottom Layer w5: R418B.2@-1658.44,1150.79 v1(-1639.57,1150.79) R402B.2@-1620.69,1150.79
NetR402C_2: R402C.2 R418C.2 U34C.5 | length 68.6
  Top Layer w5: U34C.5@-1670.38,700.79 v1(-1639.57,700.79)
  Bottom Layer w5: R418C.2@-1658.44,700.79 v1(-1639.57,700.79) R402C.2@-1620.69,700.79
NetR402D_2: R402D.2 R418D.2 U34D.5 | length 68.6
  Top Layer w5: U34D.5@-1670.38,250.79 v1(-1639.57,250.79)
  Bottom Layer w5: R418D.2@-1658.44,250.79 v1(-1639.57,250.79) R402D.2@-1620.69,250.79
NetR402E_2: R402E.2 R418E.2 U34E.5 | length 68.6
  Top Layer w5: U34E.5@-1670.38,-199.21 v1(-1639.57,-199.21)
  Bottom Layer w5: R418E.2@-1658.44,-199.21 v1(-1639.57,-199.21) R402E.2@-1620.69,-199.21
NetR402F_2: R402F.2 R418F.2 U34F.5 | length 68.6
  Top Layer w5: U34F.5@-1670.38,-649.21 v1(-1639.57,-649.21)
  Bottom Layer w5: R418F.2@-1658.44,-649.21 v1(-1639.57,-649.21) R402F.2@-1620.69,-649.21
NetR402G_2: R402G.2 R418G.2 U34G.5 | length 68.6
  Top Layer w5: U34G.5@-1670.38,-1099.21 v1(-1639.57,-1099.21)
  Bottom Layer w5: R418G.2@-1658.44,-1099.21 v1(-1639.57,-1099.21) R402G.2@-1620.69,-1099.21
NetR402H_2: R402H.2 R418H.2 U34H.5 | length 68.6
  Top Layer w5: U34H.5@-1670.38,-1549.21 v1(-1639.57,-1549.21)
  Bottom Layer w5: R418H.2@-1658.44,-1549.21 v1(-1639.57,-1549.21) R402H.2@-1620.69,-1549.21
NetR419A_2: R419A.2 U34A.6 | length 49.7
  Top Layer w5: U34A.6@-1670.38,1620.47 v1(-1639.57,1620.47)
  Bottom Layer w5: R419A.2@-1658.44,1620.47 v1(-1639.57,1620.47)
NetR419B_2: R419B.2 U34B.6 | length 49.7
  Top Layer w5: U34B.6@-1670.38,1170.47 v1(-1639.57,1170.47)
  Bottom Layer w5: R419B.2@-1658.44,1170.47 v1(-1639.57,1170.47)
NetR419C_2: R419C.2 U34C.6 | length 49.7
  Top Layer w5: U34C.6@-1670.38,720.47 v1(-1639.57,720.47)
  Bottom Layer w5: R419C.2@-1658.44,720.47 v1(-1639.57,720.47)
NetR419D_2: R419D.2 U34D.6 | length 49.7
  Top Layer w5: U34D.6@-1670.38,270.47 v1(-1639.57,270.47)
  Bottom Layer w5: R419D.2@-1658.44,270.47 v1(-1639.57,270.47)
NetR419E_2: R419E.2 U34E.6 | length 49.7
  Top Layer w5: U34E.6@-1670.38,-179.53 v1(-1639.57,-179.53)
  Bottom Layer w5: R419E.2@-1658.44,-179.53 v1(-1639.57,-179.53)
NetR419F_2: R419F.2 U34F.6 | length 49.7
  Top Layer w5: U34F.6@-1670.38,-629.53 v1(-1639.57,-629.53)
  Bottom Layer w5: R419F.2@-1658.44,-629.53 v1(-1639.57,-629.53)
NetR419G_2: R419G.2 U34G.6 | length 49.7
  Top Layer w5: U34G.6@-1670.38,-1079.53 v1(-1639.57,-1079.53)
  Bottom Layer w5: R419G.2@-1658.44,-1079.53 v1(-1639.57,-1079.53)
NetR419H_2: R419H.2 U34H.6 | length 49.7
  Top Layer w5: U34H.6@-1670.38,-1529.53 v1(-1639.57,-1529.53)
  Bottom Layer w5: R419H.2@-1658.44,-1529.53 v1(-1639.57,-1529.53)
NetR457A_1: R457A.1 U34A.55 | length 49.7
  Top Layer w5: v1(-1716.73,1464.57) U34A.55@-1716.73,1495.38
  Bottom Layer w5: v1(-1716.73,1464.57) R457A.1@-1716.73,1483.44
NetR457B_1: R457B.1 U34B.55 | length 49.7
  Top Layer w5: v1(-1716.73,1014.57) U34B.55@-1716.73,1045.38
  Bottom Layer w5: v1(-1716.73,1014.57) R457B.1@-1716.73,1033.44
NetR457C_1: R457C.1 U34C.55 | length 49.7
  Top Layer w5: v1(-1716.73,564.57) U34C.55@-1716.73,595.38
  Bottom Layer w5: v1(-1716.73,564.57) R457C.1@-1716.73,583.44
